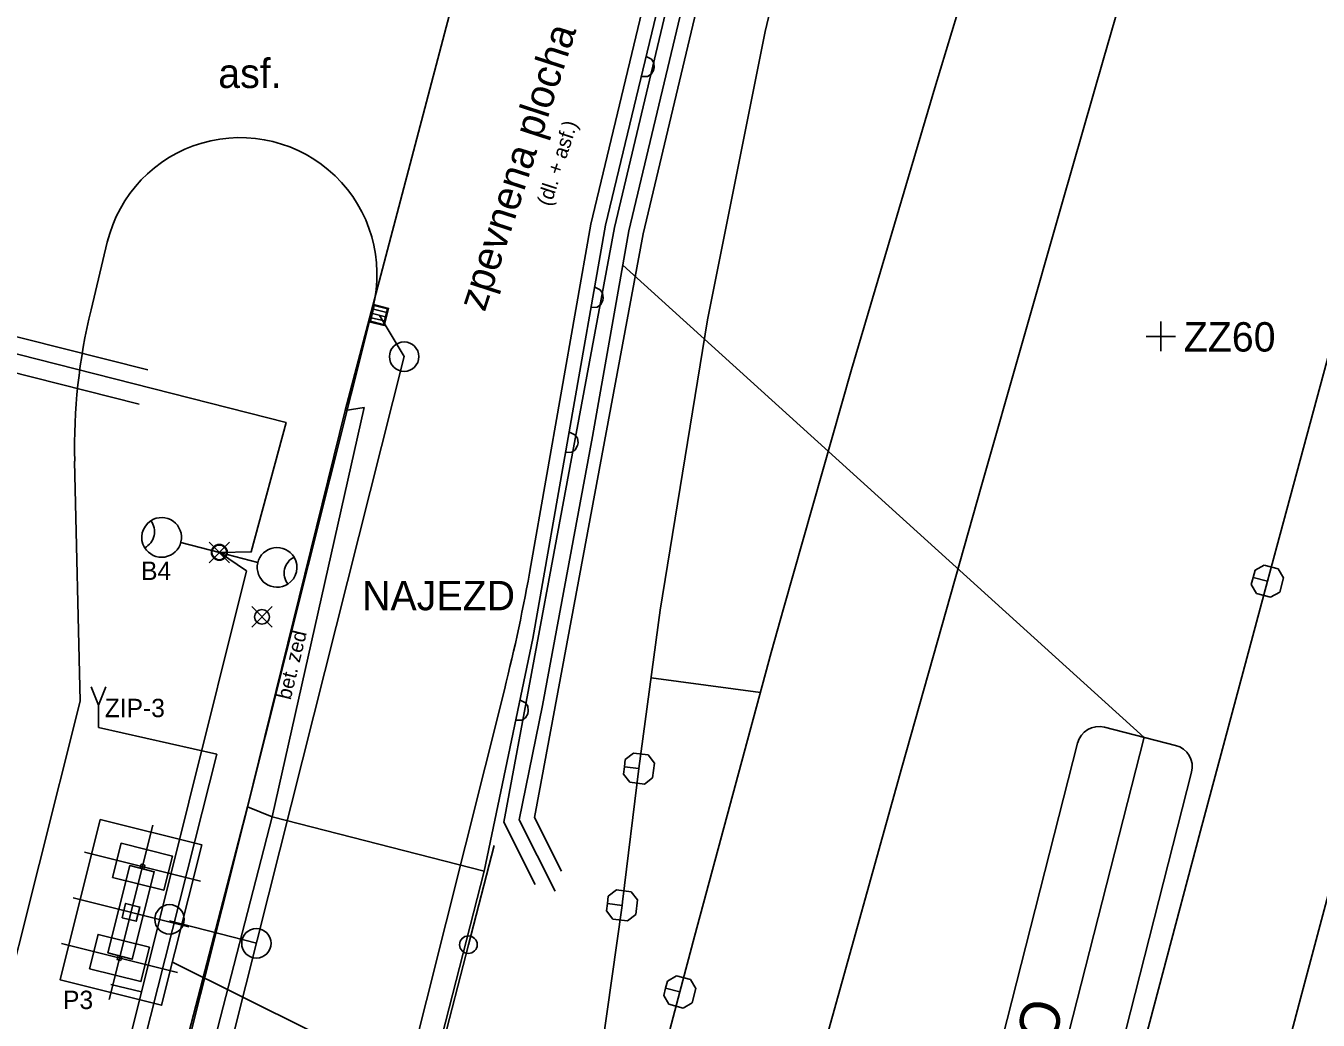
# Model space of a CAD drawing. Extents: x -733601 to -733291, y -1137892 to -1137187.
# Drawn here: x -733445.37 to -733401.43, y -1137556.95 to -1137523.14 of the extents above; entities that cross this region are included whole.
import ezdxf

# ---------------------------------------------------------------- set-up
doc = ezdxf.new("R2010")
doc.units = 0
for name, color, linetype in [('BP_ZBP_a_ZZ', 7, 'Continuous'), ('Default', 7, 'Continuous'), ('SIT_PROJ', 7, 'Continuous'), ('SIT_PUV_BUS', 7, 'Continuous'), ('SIT_PUV_ZELEZNICE', 7, 'Continuous')]:
    doc.layers.add(name, color=color, linetype=linetype)

# ---------------------------------------------------------------- blocks, each defined once
blk = doc.blocks.new('DOPRAVA_4$0$SYMB1230')
at = {"layer": 'Default'}
for p, q in [((-0.1, -0.329897), (-0.1, -0.020619)), ((0, -0.020619), (0, -0.329897)), ((0.1, -0.020619), (0.1, -0.329897)), ((-0.1, -0.325773), (-0.1, -0.329897))]:
    blk.add_line(p, q, dxfattribs=at)
for points in [[(-0.2, 0), (0.2, 0), (0.2, -0.35), (-0.2, -0.35)], [(-0.182831, -0.020619), (0.181696, -0.020619), (0.181696, -0.329897), (-0.182831, -0.329897)]]:
    blk.add_lwpolyline(points, close=True, dxfattribs=at)
blk = doc.blocks.new('novy_s_2r')
at = {"layer": 'Default'}
for p in [(502.569, 387.82), (502.559, 384.813)]:
    blk.add_line(p, (502.564, 386.316), dxfattribs=at)
blk.add_circle((502.564, 386.316), 0.298, dxfattribs=at)
blk.add_circle((502.564, 386.316), 0.298, dxfattribs=at)
blk.add_circle((502.564, 386.316), 0.298, dxfattribs=at)
blk.add_circle((502.564, 386.316), 0.298, dxfattribs=at)
for centre, radius, start, end in [((502.571, 388.57), 0.75, 46.9837, 135.4673), ((502.571, 388.57), 0.75, 46.9837, 135.4673), ((502.571, 388.57), 0.75, 135.4683, 46.9828), ((502.55, 389.547), 0.684, 221.2842, 321.1668), ((502.55, 389.547), 0.684, 221.2842, 321.1668), ((502.556, 384.063), 0.75, 315.4683, 226.9828), ((502.577, 383.086), 0.684, 41.2842, 141.1668), ((502.577, 383.086), 0.684, 41.2842, 141.1668), ((502.556, 384.063), 0.75, 226.9837, 315.4673), ((502.556, 384.063), 0.75, 226.9837, 315.4673)]:
    blk.add_arc(centre, radius, start, end, dxfattribs=at)
blk = doc.blocks.new('VY1')
at = {"layer": 'Default'}
for q in [(-50, 275), (50, 275), (0, 0)]:
    blk.add_line((0, 150), q, dxfattribs=at)
blk = doc.blocks.new('POINT_DISPLAY')
at = {"layer": 'Default'}
for p, q in [((-0.7, -0.7), (0.7, 0.7)), ((-0.7, 0.7), (0.7, -0.7))]:
    blk.add_line(p, q, dxfattribs=at)
blk.add_circle((0, 0), 0.5, dxfattribs=at)
blk = doc.blocks.new('vytyc_bod_MP')
at = {"layer": 'Default'}
blk.add_blockref('POINT_DISPLAY', (0, 0), dxfattribs=at)
blk = doc.blocks.new('T_PS_1_1_6')
at = {"layer": 'Default'}
blk.add_line((-12.486, 3.717), (12.486, 3.717), dxfattribs=at)
for points in [[(10.986, 8), (-10.986, 8)], [(-12.486, 6.5), (-12.486, 1.5)], [(12.486, 1.5), (12.486, 6.5)], [(-10.986, 0), (10.986, 0)]]:
    blk.add_lwpolyline(points, dxfattribs=at)
for centre, start, end in [((-10.986, 6.5), 90, 180), ((10.986, 6.5), 0, 90), ((-10.986, 1.5), 180, 270), ((10.986, 1.5), 270, 360)]:
    blk.add_arc(centre, 1.5, start, end, dxfattribs=at)
blk.add_text('SO', height=2.7, dxfattribs=at).set_placement((-11.75, 4.466))

msp = doc.modelspace()

# ---------------------------------------------------------------- linework, layer by layer
at = {"layer": 'BP_ZBP_a_ZZ'}
for p, q in [((-733406.781, -1137533.195), (-733406.781, -1137534.195)), ((-733407.281, -1137533.695), (-733406.281, -1137533.695))]:
    msp.add_line(p, q, dxfattribs=at)
at = {"layer": 'SIT_PROJ'}
for p, q in [((-733442.543, -1137556.25), (-733441.053, -1137550.314)), ((-733443.377, -1137551.236), (-733439.439, -1137552.225)), ((-733443.767, -1137552.788), (-733439.829, -1137553.777)), ((-733444.156, -1137554.34), (-733440.219, -1137555.329)), ((-733440.281, -1137593.122), (-733430.325, -1137554.381))]:
    msp.add_line(p, q, dxfattribs=at)
for points in [[(-733427.159, -1137551.881), (-733428.074, -1137550.062), (-733424.377, -1137530.206), (-733421.746, -1137519.1), (-733423.097, -1137516.67)], [(-733428.052, -1137552.331), (-733429.119, -1137550.211), (-733425.355, -1137529.999), (-733422.808, -1137519.247), (-733423.971, -1137517.156)], [(-733427.369, -1137552.561), (-733428.596, -1137550.137), (-733427.81, -1137546.252), (-733426.105, -1137537.1), (-733424.866, -1137530.103), (-733422.883, -1137521.79), (-733422.277, -1137519.173), (-733423.543, -1137516.897), (-733424.238, -1137518.238)], [(-733428.759, -1137520.007), (-733424.071, -1137521.184), (-733426.163, -1137529.882), (-733428.201, -1137541.484)], [(-733442.602, -1137530.495), (-733443.157, -1137532.789)], [(-733457.917, -1137622.364), (-733458.777, -1137620.095), (-733456.339, -1137614.218), (-733457.273, -1137613.333), (-733455.913, -1137612.939), (-733454.69, -1137608.9), (-733452.562, -1137600.661), (-733449.967, -1137590.732), (-733451.007, -1137589.721), (-733449.679, -1137589.475), (-733444.067, -1137566.075), (-733444.902, -1137565.405), (-733443.754, -1137565.269), (-733437.875, -1137541.673), (-733438.793, -1137541.042), (-733437.71, -1137541.027), (-733436.525, -1137536.63), (-733452.133, -1137532.662), (-733452.807, -1137531.541)], [(-733425.074, -1137531.276), (-733407.349, -1137547.331), (-733407.349, -1137547.331)], [(-733451.176, -1137532.326), (-733441.226, -1137534.835)], [(-733456.299, -1137623.235), (-733433.573, -1137532.72)], [(-733432.51, -1137534.385), (-733433.36, -1137532.963)], [(-733451.469, -1137533.49), (-733441.52, -1137535.998)], [(-733432.51, -1137534.385), (-733444.427, -1137581.731), (-733459.039, -1137578.132)], [(-733443.713, -1137537.937), (-733443.53, -1137546.097), (-733458.871, -1137607.201), (-733463.551, -1137615.482)], [(-733429.102, -1137545.713), (-733449.631, -1137627.477)], [(-733442.902, -1137546.994), (-733438.875, -1137547.904)], [(-733457.917, -1137622.364), (-733458.523, -1137621.757), (-733455.851, -1137614.377), (-733455.422, -1137613.019), (-733451.725, -1137599.481), (-733449.522, -1137590.912), (-733449.164, -1137589.482), (-733443.392, -1137565.741), (-733438.875, -1137547.904)], [(-733442.84, -1137550.123), (-733439.387, -1137550.99), (-733440.756, -1137556.441), (-733444.209, -1137555.574), (-733442.84, -1137550.124)], [(-733430.325, -1137554.381), (-733429.453, -1137551.012)], [(-733441.36, -1137551.811), (-733441.328, -1137551.682), (-733441.457, -1137551.649), (-733441.489, -1137551.778), (-733441.36, -1137551.811)], [(-733440.487, -1137553.565), (-733437.534, -1137554.334)], [(-733442.139, -1137554.914), (-733442.107, -1137554.785), (-733442.236, -1137554.753), (-733442.268, -1137554.882), (-733442.139, -1137554.914)], [(-733440.387, -1137554.973), (-733416.748, -1137566.741), (-733416.748, -1137566.741)], [(-733441.443, -1137555.985), (-733442.486, -1137555.74)]]:
    msp.add_lwpolyline(points, dxfattribs=at)
for points in [[(-733442.427, -1137552.094), (-733442.135, -1137550.93), (-733440.389, -1137551.368), (-733440.682, -1137552.532)], [(-733442.588, -1137554.664), (-733441.841, -1137551.69), (-733441.007, -1137551.899), (-733441.754, -1137554.874)], [(-733442.101, -1137553.464), (-733441.98, -1137552.979), (-733441.495, -1137553.101), (-733441.616, -1137553.586)], [(-733443.207, -1137555.197), (-733442.914, -1137554.033), (-733441.169, -1137554.471), (-733441.461, -1137555.635)]]:
    msp.add_lwpolyline(points, close=True, dxfattribs=at)
for centre, radius in [((-733432.51, -1137534.386), 0.5), ((-733440.487, -1137553.519), 0.5), ((-733437.534, -1137554.335), 0.5), ((-733430.325, -1137554.381), 0.3)]:
    msp.add_circle(centre, radius, dxfattribs=at)
for centre, radius, start, end in [((-733438.083, -1137531.588), 4.65, 345.9059, 166.406), ((-733423.717, -1137537.49), 20, 166.4056, 181.2822), ((-733487.295, -1137531.102), 59.999, 345.90587, 350.03621)]:
    msp.add_arc(centre, radius, start, end, dxfattribs=at)
at = {"layer": 'SIT_PUV_BUS'}
for p, q in [((-733419.1, -1137502.64), (-733425.66, -1137529.91)), ((-733429.17, -1137515.92), (-733434.52, -1137536.22)), ((-733424.278, -1137524.18), (-733424.095, -1137524.275)), ((-733424.031, -1137524.65), (-733424.115, -1137524.785)), ((-733424.095, -1137524.275), (-733424.022, -1137524.396)), ((-733424.008, -1137524.553), (-733424.031, -1137524.65)), ((-733424.022, -1137524.396), (-733424.008, -1137524.553)), ((-733424.236, -1137524.858), (-733424.442, -1137524.86)), ((-733424.115, -1137524.785), (-733424.236, -1137524.858)), ((-733425.66, -1137529.91), (-733428.13, -1137543.97)), ((-733426.029, -1137532.025), (-733425.841, -1137532.109)), ((-733425.841, -1137532.109), (-733425.76, -1137532.225)), ((-733425.754, -1137532.48), (-733425.829, -1137532.619)), ((-733425.76, -1137532.225), (-733425.737, -1137532.382)), ((-733425.737, -1137532.382), (-733425.754, -1137532.48)), ((-733425.945, -1137532.7), (-733426.151, -1137532.715)), ((-733425.829, -1137532.619), (-733425.945, -1137532.7)), ((-733434.52, -1137536.22), (-733437.84, -1137549.69)), ((-733433.87, -1137536.12), (-733437, -1137550.03)), ((-733434.52, -1137536.22), (-733433.87, -1137536.12)), ((-733426.889, -1137536.955), (-733426.701, -1137537.039)), ((-733426.701, -1137537.039), (-733426.62, -1137537.155)), ((-733426.614, -1137537.41), (-733426.689, -1137537.549)), ((-733426.62, -1137537.155), (-733426.597, -1137537.312)), ((-733426.597, -1137537.312), (-733426.614, -1137537.41)), ((-733426.805, -1137537.63), (-733427.011, -1137537.645)), ((-733426.689, -1137537.549), (-733426.805, -1137537.63)), ((-733428.13, -1137543.97), (-733429.79, -1137551.88)), ((-733428.568, -1137546.068), (-733428.382, -1137546.158)), ((-733428.382, -1137546.158), (-733428.305, -1137546.276)), ((-733428.308, -1137546.531), (-733428.388, -1137546.668)), ((-733428.287, -1137546.433), (-733428.308, -1137546.531)), ((-733428.305, -1137546.276), (-733428.287, -1137546.433)), ((-733428.506, -1137546.745), (-733428.712, -1137546.752)), ((-733428.388, -1137546.668), (-733428.506, -1137546.745)), ((-733437.84, -1137549.69), (-733442.47, -1137567.55)), ((-733437.84, -1137549.69), (-733437, -1137550.03)), ((-733445.62, -1137583.47), (-733437, -1137550.03)), ((-733429.79, -1137551.88), (-733437, -1137550.03)), ((-733429.79, -1137551.88), (-733440.4, -1137593.2))]:
    msp.add_line(p, q, dxfattribs=at)
at = {"layer": 'SIT_PUV_ZELEZNICE'}
for p, q in [((-733403.639, -1137541.891), (-733403.574, -1137541.65)), ((-733403.574, -1137541.65), (-733403.268, -1137541.473)), ((-733403.268, -1137541.473), (-733402.785, -1137541.603)), ((-733402.785, -1137541.603), (-733402.608, -1137541.91)), ((-733403.704, -1137542.133), (-733403.639, -1137541.891)), ((-733403.527, -1137542.439), (-733403.704, -1137542.133)), ((-733403.156, -1137542.021), (-733403.639, -1137541.891)), ((-733402.608, -1137541.91), (-733402.738, -1137542.392)), ((-733403.045, -1137542.569), (-733403.527, -1137542.439)), ((-733402.738, -1137542.392), (-733403.045, -1137542.569)), ((-733420.395, -1137545.807), (-733424.112, -1137545.309)), ((-733424.991, -1137548.085), (-733424.712, -1137547.867)), ((-733424.712, -1137547.867), (-733424.216, -1137547.929)), ((-733424.216, -1137547.929), (-733423.998, -1137548.208)), ((-733425.052, -1137548.581), (-733425.021, -1137548.333)), ((-733425.021, -1137548.333), (-733424.991, -1137548.085)), ((-733424.525, -1137548.394), (-733425.021, -1137548.333)), ((-733423.998, -1137548.208), (-733424.06, -1137548.704)), ((-733424.835, -1137548.86), (-733425.052, -1137548.581)), ((-733424.06, -1137548.704), (-733424.338, -1137548.921)), ((-733424.338, -1137548.921), (-733424.835, -1137548.86)), ((-733425.597, -1137552.984), (-733425.567, -1137552.736)), ((-733425.567, -1137552.736), (-733425.288, -1137552.518)), ((-733425.288, -1137552.518), (-733424.791, -1137552.58)), ((-733424.791, -1137552.58), (-733424.574, -1137552.859)), ((-733425.628, -1137553.232), (-733425.597, -1137552.984)), ((-733425.411, -1137553.511), (-733425.628, -1137553.232)), ((-733425.101, -1137553.045), (-733425.597, -1137552.984)), ((-733424.574, -1137552.859), (-733424.636, -1137553.355)), ((-733424.914, -1137553.572), (-733425.411, -1137553.511)), ((-733424.636, -1137553.355), (-733424.914, -1137553.572)), ((-733423.683, -1137556.104), (-733423.62, -1137555.862)), ((-733423.62, -1137555.862), (-733423.557, -1137555.62)), ((-733423.136, -1137555.989), (-733423.62, -1137555.862)), ((-733423.557, -1137555.62), (-733423.252, -1137555.442)), ((-733423.252, -1137555.442), (-733422.768, -1137555.569)), ((-733422.768, -1137555.569), (-733422.589, -1137555.874)), ((-733423.505, -1137556.409), (-733423.683, -1137556.104)), ((-733422.589, -1137555.874), (-733422.716, -1137556.358)), ((-733423.021, -1137556.536), (-733423.505, -1137556.409)), ((-733422.716, -1137556.358), (-733423.021, -1137556.536))]:
    msp.add_line(p, q, dxfattribs=at)
for points in [[(-733432.613, -1137592.177), (-733430.241, -1137582.464), (-733428.195, -1137572.675), (-733426.476, -1137562.825), (-733425.101, -1137553.045), (-733425.086, -1137552.922), (-733424.525, -1137548.394), (-733423.804, -1137543.005), (-733422.199, -1137533.135), (-733420.237, -1137523.33), (-733417.92, -1137513.602), (-733417.278, -1137511.157), (-733415.349, -1137503.939), (-733412.766, -1137494.278), (-733410.183, -1137484.617), (-733407.6, -1137474.957), (-733405.017, -1137465.296), (-733402.434, -1137455.636), (-733401.342, -1137451.549), (-733399.798, -1137445.99), (-733397.493, -1137438.369), (-733396.877, -1137436.426), (-733393.987, -1137427.309)], [(-733424.195, -1137560.031), (-733423.136, -1137555.989), (-733422.64, -1137554.102), (-733420.028, -1137544.45), (-733419.6, -1137542.91), (-733417.303, -1137534.828), (-733414.464, -1137525.239), (-733413.695, -1137522.711), (-733413.646, -1137522.55), (-733411.495, -1137515.69), (-733408.347, -1137506.199), (-733407.141, -1137502.714), (-733405.019, -1137496.769), (-733401.513, -1137487.404), (-733399.59, -1137482.49), (-733397.847, -1137478.1), (-733394.158, -1137468.806), (-733394.03, -1137468.485), (-733390.544, -1137459.482), (-733387.094, -1137450.096), (-733383.809, -1137440.651), (-733380.689, -1137431.15), (-733380.109, -1137429.318)], [(-733408.191, -1137579.632), (-733407.168, -1137575.72), (-733404.629, -1137566.048), (-733404.003, -1137563.67), (-733402.076, -1137556.379), (-733400.028, -1137548.693), (-733399.499, -1137546.716), (-733396.898, -1137537.061), (-733394.522, -1137528.325), (-733394.273, -1137527.412), (-733391.623, -1137517.769), (-733389.167, -1137508.912), (-733388.95, -1137508.133), (-733388.909, -1137507.986), (-733386.266, -1137498.5), (-733383.849, -1137489.821)], [(-733424.808, -1137581.736), (-733423.595, -1137577.27), (-733420.948, -1137567.626), (-733420.168, -1137564.801), (-733418.278, -1137557.99), (-733415.583, -1137548.36), (-733412.864, -1137538.736), (-733410.121, -1137529.12), (-733408.737, -1137524.299), (-733407.354, -1137519.51), (-733404.564, -1137509.907), (-733401.749, -1137500.312), (-733398.91, -1137490.723)], [(-733412.782, -1137578.384), (-733410.545, -1137569.839), (-733410.013, -1137567.818), (-733410.012, -1137567.811), (-733407.996, -1137560.169), (-733405.429, -1137550.505), (-733403.156, -1137542.021), (-733402.84, -1137540.845), (-733400.227, -1137531.193), (-733399.104, -1137527.074), (-733397.59, -1137521.547), (-733394.93, -1137511.907), (-733392.245, -1137502.274), (-733389.536, -1137492.648)]]:
    msp.add_lwpolyline(points, dxfattribs=at)

# ---------------------------------------------------------------- block references
at = {"layer": 'SIT_PROJ'}
for name, p, xscale, yscale, rotation in [('DOPRAVA_4$0$SYMB1230', (-733433.62, -1137532.907), 1.500000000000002, 1.5000000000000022, 75.90589099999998), ('novy_s_2r', (-733214.217, -1138065.477), 0.9, 0.8999999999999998, 75.63258201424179), ('T_PS_1_1_6', (-733407.092, -1137553.839), 0.4999999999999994, 0.4999999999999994, 75.68569569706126)]:
    msp.add_blockref(name, p, dxfattribs=dict(at, xscale=xscale, yscale=yscale, rotation=rotation))
for name, p, xscale, yscale in [('vytyc_bod_MP', (-733438.793, -1137541.042), 0.5, 0.5), ('vytyc_bod_MP', (-733437.343, -1137543.234), 0.5, 0.5), ('VY1', (-733442.9, -1137546.992), 0.005, 0.005)]:
    msp.add_blockref(name, p, dxfattribs=dict(at, xscale=xscale, yscale=yscale))

# ---------------------------------------------------------------- texts
at = {"layer": 'BP_ZBP_a_ZZ'}
msp.add_text('ZZ60', height=1, dxfattribs=at).set_placement((-733406, -1137534.213))
at = {"layer": 'SIT_PROJ'}
for s, p in [('B4', (-733441.453, -1137541.979)), ('ZIP-3', (-733442.689, -1137546.645)), ('P3', (-733444.107, -1137556.571))]:
    msp.add_text(s, height=0.625, rotation=360, dxfattribs=at).set_placement(p)
at = {"layer": 'SIT_PUV_BUS'}
for s, height, rotation, p in [('zpevnena plocha', 1, 72, (-733429.77, -1137532.89)), ('(dl. + asf.)', 0.5, 72, (-733427.53, -1137529.3)), ('bet. zed', 0.5, 76.5, (-733436.37, -1137546.08))]:
    msp.add_text(s, height=height, rotation=rotation, dxfattribs=at).set_placement(p)
for s, p in [('asf.', (-733438.83, -1137525.25)), ('NAJEZD', (-733433.94, -1137543.01))]:
    msp.add_text(s, height=1, dxfattribs=at).set_placement(p)

doc.saveas('drawing.dxf')
